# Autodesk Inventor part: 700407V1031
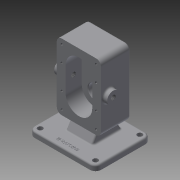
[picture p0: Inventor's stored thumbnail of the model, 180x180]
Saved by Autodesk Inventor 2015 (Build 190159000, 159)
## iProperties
Created: 2020-04
Part Number: 700407V1031
Material: 일반
Document SubType Name: Modeling
Designer: now
Density: 1 g/cm^3
Appearance: 기본값
Mass: 545.387 g
Surface Area: 818.353 cm^2
Volume: 545.387 cm^3
Author: now
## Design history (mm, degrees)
sketch "스케치1"
  geometry: L1 (40, -60)-(-40, -60); L2 (-40, -60)-(-40, 60); L3 (-40, 60)-(40, 60); L4 (40, 60)-(40, -60); L5 (40, -60)-(-40, 60); L6 (-40, -60)-(40, 60); 1 further point
  constraints: 12 end point, 2 midpoint, 2 parallel, 1 horizontal, 1 perpendicular
  dimensions: "d0" = 80 distance of L2.end L3.end; "d1" = 120 distance of L3.end L1.start
extrude "돌출1" new body sketch "스케치1" distance "d2" = 53; taper "d3" = 0 deg
sketch "스케치2"
  geometry: L1 (0, -22)-(0, 22); L2 (-24, -22)-(-24, 22); L3 (24, 22)-(24, -22); A1 r 24 centre (0, -22) between (-24, -22) and (24, -22); A2 r 24 centre (0, 22) between (24, 22) and (-24, 22); 1 further point
  constraints: 8 end point, 4 point on circle, 4 tangent, 2 centre point, 1 midpoint, 1 parallel, 1 vertical
  dimensions: "d4" = 24 radius of A2; "d5" = 44 distance of L1.start L1.end
extrude "돌출2" cut sketch "스케치2" distance "d6" = 29; taper "d7" = 0 deg
sketch "스케치3"
  geometry: C1 r 19 at (0, -22); 1 further point
  constraints: 1 centre point, 1 vertical alignment
  dimensions: "d8" = 38 diameter of C1; "d9" = 22 distance of point (0, 0) C1.centre
extrude "돌출3" join sketch "스케치3" distance "d10" = 17; taper "d11" = 0 deg
sketch "스케치4"
  geometry: C1 r 19 at (0, 0) reference; 1 further point
hole "구멍1" sketch "스케치4" at (0, 0) diameter "d12" = 17; stored, may be unused: countersink angle "d16" = 90 deg, drill point angle "d18" = 118 deg; dims "d13" = 6, "d14" = 28, "d15" = 7.3, "d17" = 8
sketch "스케치5"
  geometry: C1 r 12.5 at (0, 22); A1 r 24 centre (0, 22) between (24, 22) and (-24, 22) reference; 1 further point
  constraints: 1 centre point, 1 coincident
  dimensions: "d19" = 25 diameter of C1
extrude "돌출4" cut sketch "스케치5" distance "d20" = 15; taper "d21" = 0 deg
sketch "스케치6"
  geometry: C1 r 12.5 at (0, -22); A1 r 24 centre (0, -22) between (-24, -22) and (24, -22) reference; 1 further point
  constraints: 1 centre point, 1 coincident
  dimensions: "d22" = 25 diameter of C1
extrude "돌출5" cut sketch "스케치6" distance "d23" = 15; taper "d24" = 0 deg
node "작업 평면1"
node "작업 평면2"
sketch "스케치7"
  geometry: L1 (100, -30)-(-20, -30); L2 (-20, -30)-(-20, 70); L3 (-20, 70)-(100, 70); L4 (100, 70)-(100, -30); L5 (100, -30)-(-20, 70); L6 (-20, -30)-(100, 70); L7 (59, 70)-(21, 70) reference; 3 further points
  constraints: 12 end point, 3 midpoint, 2 parallel, 1 horizontal, 1 horizontal alignment, 1 perpendicular, 1 vertical alignment
  dimensions: "d26" = 120 distance between parallel lines of L4 L2; "d27" = 100 distance of L1.end L2.end
extrude "돌출6" join sketch "스케치7" distance "d29" = 10; taper "d30" = 0 deg
sketch "스케치8"
  geometry: L1 (100, 70)-(-20, 70) reference; L2 (64, 0)-(16, 0); L3 (16, 0)-(16, 53); L4 (16, 53)-(64, 53); L5 (64, 53)-(64, 0); L6 (64, 0)-(16, 53); L7 (16, 0)-(64, 53); 3 further points
  constraints: 12 end point, 3 midpoint, 2 parallel, 1 horizontal, 1 perpendicular, 1 vertical alignment
  dimensions: "d31" = 48 distance of L3.end L4.end; "d32" = 53 distance of L2.end L3.end; "d33" = 17 distance between parallel lines of L4 L1
extrude "돌출7" new body sketch "스케치8" distance "d34" = 30; taper "d35" = 0 deg
feature "면 기울기1" dims angle "d36" = 30 deg
feature "결합1"
  node "솔리드2"
sketch "스케치9"
  geometry: L1 (150, 70)-(150, -30) reference; C1 r 11 at (60, 14); 1 further point
  constraints: 1 centre point
  dimensions: "d37" = 22 diameter of C1; "d38" = 90 distance from line of L1 C1.centre; "d39" = 14 distance of C1.centre point (60, 0)
extrude "돌출8" join sketch "스케치9" distance "d40" = 8; taper "d41" = 0 deg
sketch "스케치10"
  geometry: C1 r 11 at (0, 0) reference; 1 further point
hole "구멍2" sketch "스케치10" at (0, 0) diameter "d42" = 8.376; stored, may be unused: countersink angle "d46" = 90 deg, drill point angle "d48" = 118 deg; dims "d43" = 20, "d44" = 28, "d45" = 7.3, "d47" = 27.3
fillet "모깎기1" dims "d49" = 3
fillet "모깎기2" dims "d50" = 9
sketch "스케치11"
  geometry: A1 r 9 centre (-31, -51) between (-40, -51) and (-31, -60) reference; A2 r 9 centre (31, -51) between (31, -60) and (40, -51) reference; A3 r 9 centre (31, 51) between (40, 51) and (31, 60) reference; A4 r 9 centre (-31, 51) between (-31, 60) and (-40, 51) reference; 1 further point
hole "구멍3" sketch "스케치11" at (-31, 51), (31, 51), (-31, -51), (31, -51) diameter "d51" = 4.134; stored, may be unused: countersink angle "d55" = 90 deg, drill point angle "d57" = 118 deg; dims "d52" = 10, "d53" = 28, "d54" = 7.3, "d56" = 12
sketch "스케치12"
  geometry: C1 r 2.067 at (-31, 51) reference; C2 r 2.067 at (31, 51) reference; 5 further points
  constraints: 4 vertical alignment
  dimensions: "d58" = 44 distance of point (-31, -22) point (-31, 22); "d59" = 22 vertical distance of point (-31, 22) point (0, 0); "d60" = 44 distance of point (31, -22) point (31, 22); "d61" = 22 vertical distance of point (31, -22) point (0, 0)
hole "구멍4" sketch "스케치12" at (-31, 22), (-31, -22), (31, 22), (31, -22) diameter "d62" = 4.134; stored, may be unused: countersink angle "d66" = 90 deg, drill point angle "d68" = 118 deg; dims "d63" = 10, "d64" = 28, "d65" = 7.3, "d67" = 12
chamfer "모따기1" distance "d69" = 0.7; stored, may be unused: second distance "d70" = 2, angle "d71" = 30 deg
fillet "모깎기3" dims "d72" = 0.5
chamfer "모따기2" distance "d73" = 1; stored, may be unused: second distance "d74" = 2, angle "d75" = 30 deg
fillet "모깎기4" dims "d76" = 10
sketch "스케치13"
  geometry: A1 r 10 centre (-10, 60) between (-10, 70) and (-20, 60) reference; A2 r 10 centre (-10, -20) between (-20, -20) and (-10, -30) reference; A3 r 10 centre (90, -20) between (90, -30) and (100, -20) reference; A4 r 10 centre (90, 60) between (100, 60) and (90, 70) reference; 1 further point
hole "구멍5" sketch "스케치13" at (-10, -20), (-10, 60), (90, -20), (90, 60) diameter "d77" = 9; stored, may be unused: countersink angle "d81" = 90 deg, drill point angle "d83" = 118 deg; dims "d78" = 6, "d79" = 4, "d80" = 2, "d82" = 8
fillet "모깎기5" dims "d84" = 3
fillet "모깎기6" dims "d85" = 3
fillet "모깎기7" dims "d86" = 3
fillet "모깎기8" dims "d87" = 3
fillet "모깎기9" dims "d88" = 3
sketch "스케치14"
  geometry: L1 (-10, -30)-(90, -30) reference; L2 (-20, 60)-(-20, -20) reference; 2 further points
  constraints: 1 other
  dimensions: "d89" = 10 distance from line of L1 point (40, -20); "d90" = 60 distance from line of point (40, -20) L2
feature "엠보싱1" sketch "스케치14" dims "d91" = 0.5, "d92" = 0
fillet "모깎기10" dims "d93" = 3
node "솔리드1"
mirror "대칭1"
